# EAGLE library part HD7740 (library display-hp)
LED DISPLAY 1-character 7 segment, decimal point right
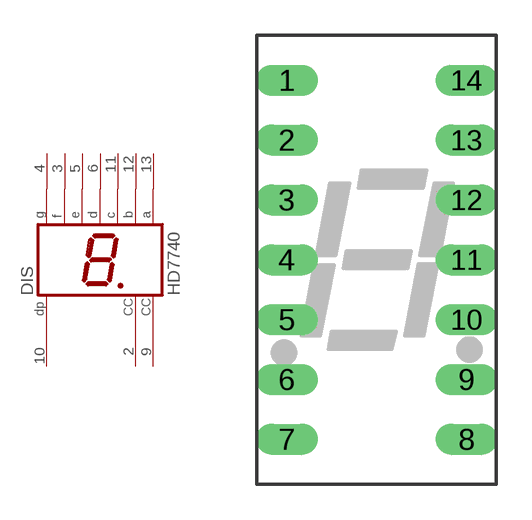
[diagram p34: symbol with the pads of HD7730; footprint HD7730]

Designator prefix DIS

## HD7740 (OC_FARNELL: unknown; OC_NEWARK: unknown)  [HD7730]
2  CC  pas
3  F  pas
4  G  pas
5  E  pas
6  D  pas
9  CC  pas
10  DP  pas
11  C  pas
12  B  pas
13  A  pas

## Footprint HD7730 (pad centres in mm)
LED DISPLAY 8-mm 1 character 7 segment, 2 decimal points
drill 0.813 long: 1 -3.81,7.62; 2 -3.81,5.08; 3 -3.81,2.54; 4 -3.81,0; 5 -3.81,-2.54; 6 -3.81,-5.08; 7 -3.81,-7.62; 8 3.81,-7.62; 9 3.81,-5.08; 10 3.81,-2.54; 11 3.81,0; 12 3.81,2.54; 13 3.81,5.08; 14 3.81,7.62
